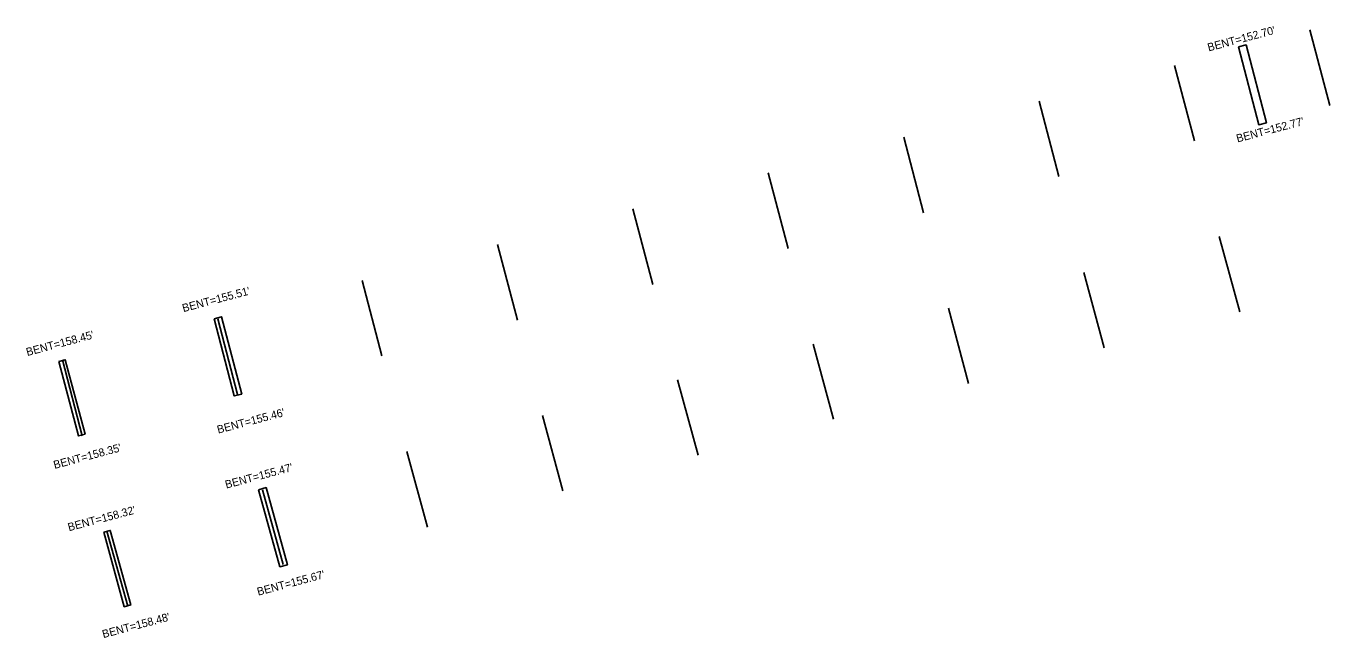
# Model space of a CAD drawing. Extents: x 2107167 to 2121551, y 865392 to 868477.
# Drawn here: x 2111419 to 2112071, y 867437 to 867743 of the extents above; entities that cross this region are included whole.
import ezdxf

# ---------------------------------------------------------------- set-up
doc = ezdxf.new("R2010")
doc.units = 0
for name, color, linetype in [('RD_EX_Bridge', 7, 'Continuous'), ('RD_EX_Bridge_txCode', 7, 'Continuous'), ('RD_EX_Conc', 7, 'Continuous')]:
    doc.layers.add(name, color=color, linetype=linetype)

msp = doc.modelspace()

# ---------------------------------------------------------------- linework, layer by layer
at = {"layer": 'RD_EX_Bridge'}
for p, q in [((2112061.12, 867741.49), (2112071.08, 867703.56)), ((2111993.39, 867723.56), (2112003.34, 867685.86)), ((2111925.72, 867705.72), (2111935.66, 867668.01)), ((2111858.14, 867687.76), (2111867.99, 867649.92)), ((2111790.4, 867669.87), (2111800.35, 867631.99)), ((2111722.72, 867651.96), (2111732.69, 867614.12)), ((2112015.8, 867638), (2112026.01, 867600.42)), ((2111655.01, 867634.04), (2111665.05, 867596.29)), ((2111948.11, 867620.13), (2111958.34, 867582.38)), ((2111587.4, 867616.03), (2111597.28, 867578.39)), ((2111880.39, 867602.17), (2111890.53, 867564.61)), ((2111515.24, 867596.84), (2111525.15, 867559.09)), ((2111812.82, 867584.29), (2111822.96, 867546.71)), ((2111437.59, 867576.33), (2111447.47, 867538.44)), ((2111745.1, 867566.34), (2111755.32, 867528.68)), ((2111677.49, 867548.47), (2111687.65, 867510.86)), ((2111609.79, 867530.49), (2111620, 867492.73)), ((2111537.64, 867511.3), (2111547.95, 867474.04)), ((2111459.75, 867490.67), (2111470.24, 867453.2))]:
    msp.add_line(p, q, dxfattribs=at)
at = {"layer": 'RD_EX_Conc'}
for points in [[(2112025.32, 867732.89), (2112035.55, 867693.92), (2112039.37, 867694.92), (2112029.15, 867733.89)], [(2112025.32, 867732.89), (2112035.55, 867693.92), (2112039.37, 867694.92), (2112029.15, 867733.89)], [(2111513.44, 867596.94), (2111523.51, 867558.31), (2111527.22, 867559.28), (2111517.15, 867597.9)], [(2111435.82, 867575.58), (2111445.73, 867538.32), (2111448.96, 867539.18), (2111439.06, 867576.44)], [(2111535.64, 867511.4), (2111546.29, 867472.87), (2111550.04, 867473.91), (2111539.39, 867512.44)], [(2111458.25, 867490.11), (2111468.51, 867452.9), (2111471.76, 867453.8), (2111461.5, 867491.01)]]:
    msp.add_lwpolyline(points, close=True, dxfattribs=at)

# ---------------------------------------------------------------- texts
at = {"layer": 'RD_EX_Bridge_txCode'}
for s, p in [("BENT=152.70'", (2112010.49, 867730.61)), ("BENT=152.77'", (2112024.88, 867685.07)), ("BENT=155.51'", (2111498.08, 867600.21)), ("BENT=158.45'", (2111420.06, 867578.25)), ("BENT=155.46'", (2111515.48, 867539.44)), ("BENT=158.35'", (2111433.73, 867521.79)), ("BENT=155.47'", (2111519.51, 867511.94)), ("BENT=158.32'", (2111440.9, 867490.63)), ("BENT=155.67'", (2111535.46, 867458.38)), ("BENT=158.48'", (2111458.08, 867437.15))]:
    msp.add_text(s, height=4, rotation=14.85803, dxfattribs=at).set_placement(p)

doc.saveas('drawing.dxf')
